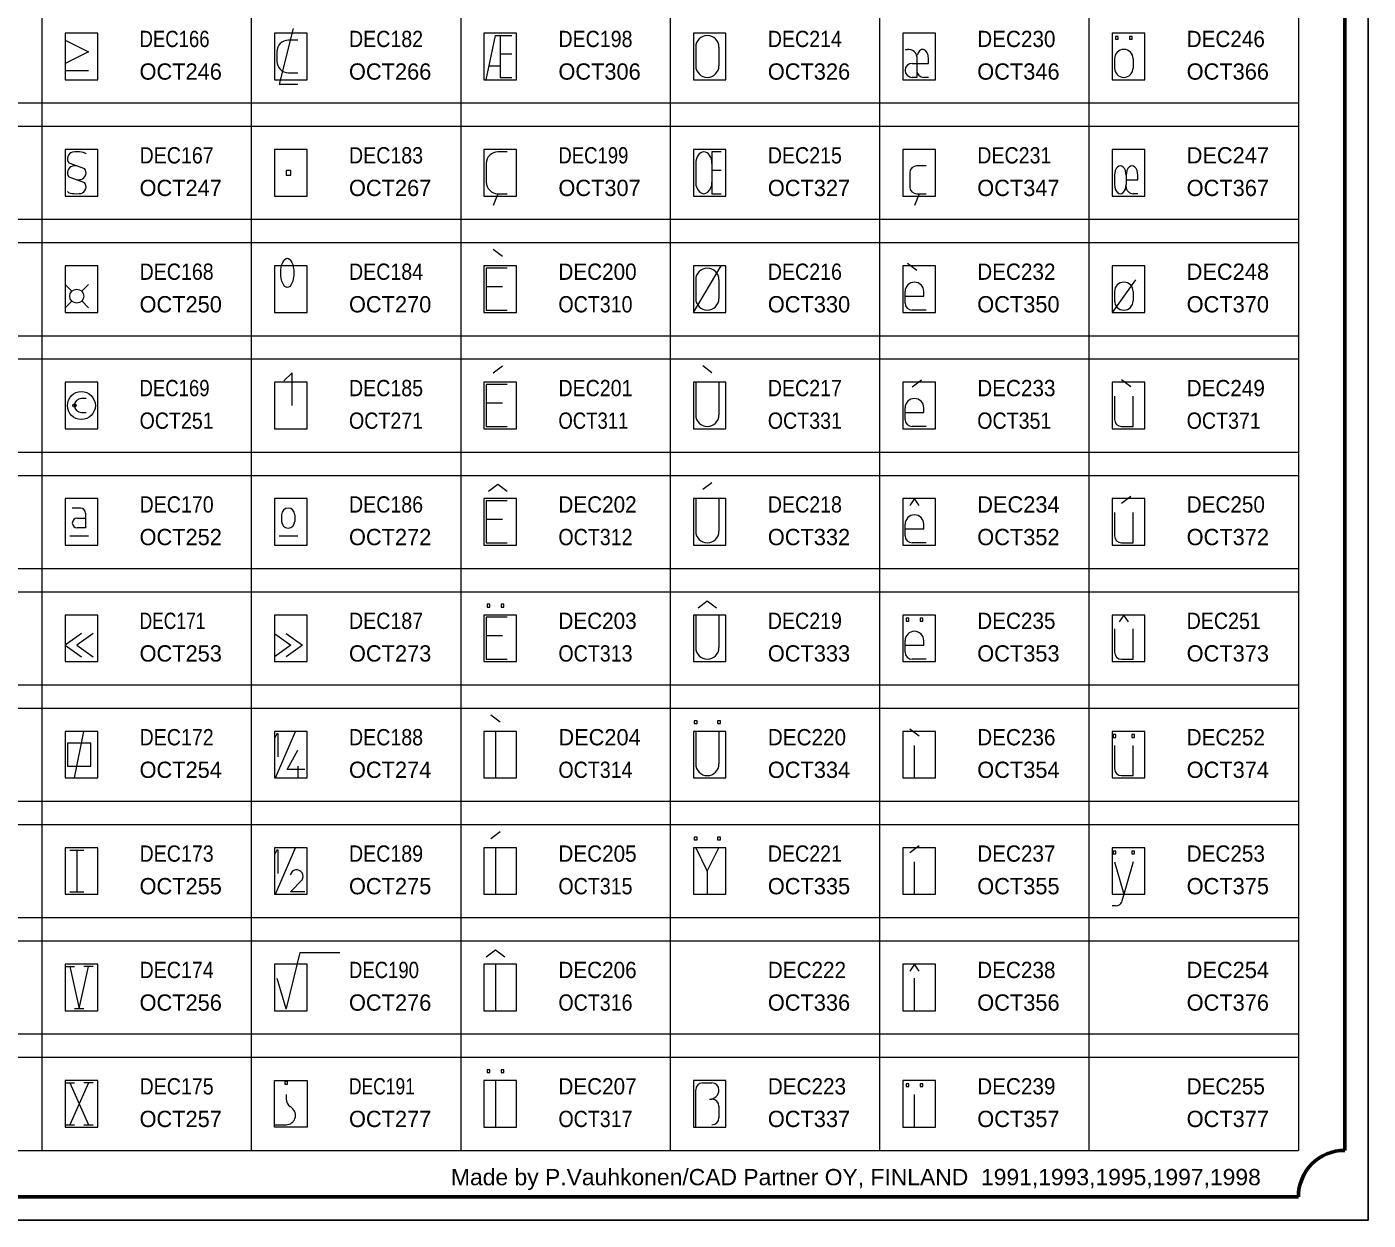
# Model space of a CAD drawing. Extents: x -200 to 7300, y -200 to 4800.
# Drawn here: x 4418 to 7300, y -200 to 2364 of the extents above; entities that cross this region are included whole.
import ezdxf
from ezdxf.enums import TextEntityAlignment as Align

# ---------------------------------------------------------------- set-up
doc = ezdxf.new("R2010")
doc.units = 0
doc.header["$LTSCALE"] = 14
doc.header["$PDMODE"] = 32
doc.header["$PDSIZE"] = 7
for name, color, linetype, lineweight in [('1', 7, 'Continuous', 13), ('5', 7, 'Continuous', 40), ('6', 7, 'Continuous', 13), ('63', 7, 'Continuous', 13)]:
    doc.layers.add(name, color=color, linetype=linetype, lineweight=lineweight)
doc.layers.add('10', color=7, linetype='Continuous')
doc.layers.add('11', color=7, linetype='Continuous')

msp = doc.modelspace()

# ---------------------------------------------------------------- linework, layer by layer
at = {"layer": '1'}
for p, q in [((5000, 2335), (4980, 2335)), ((4955, 2310), (4955, 2290)), ((5855, 2320), (5855, 2280)), ((5905, 2320), (5905, 2280)), ((6305, 2315), (6310, 2315)), ((5411, 2280), (5435, 2280)), ((5460, 2305), (5435, 2305)), ((6755, 2295), (6755, 2275)), ((6795, 2295), (6795, 2275)), ((4500, 2270), (4550, 2270)), ((4980, 2265), (5000, 2265)), ((6355, 2255), (6345, 2255)), ((5450, 2095), (5430, 2095)), ((4508, 2071), (4542, 2059)), ((5405, 2070), (5405, 2030)), ((5855, 2070), (5855, 2030)), ((5910, 2055), (5890, 2055)), ((6315, 2050), (6315, 2020)), ((6350, 2065), (6330, 2065)), ((4508, 2041), (4542, 2029)), ((6755, 2045), (6755, 2025)), ((6780, 2045), (6780, 2025)), ((5430, 2005), (5420, 1980)), ((5430, 2005), (5450, 2005)), ((6335, 2005), (6325, 1980)), ((6330, 2005), (6350, 2005)), ((6805, 2005), (6795, 2005)), ((5440, 1870), (5420, 1885)), ((5850, 1750), (5910, 1850)), ((6330, 1840), (6310, 1855)), ((5855, 1820), (5855, 1780)), ((5905, 1820), (5905, 1780)), ((6800, 1820), (6750, 1750)), ((4500, 1810), (4514.4, 1795.6)), ((4550, 1810), (4535.6, 1795.6)), ((5440, 1805), (5405, 1805)), ((6305, 1770), (6305, 1795)), ((6755, 1795), (6755, 1775)), ((6795, 1795), (6795, 1775)), ((4500, 1760), (4514.4, 1774.4)), ((4550, 1760), (4536, 1775)), ((6350, 1755), (6320, 1755)), ((5420, 1620), (5440, 1635)), ((5890, 1620), (5870, 1635)), ((5855, 1600), (5855, 1530)), ((5905, 1600), (5905, 1530)), ((6320, 1590), (6340, 1605)), ((6790, 1590), (6770, 1605)), ((4545, 1565), (4535, 1565)), ((6755, 1570), (6755, 1520)), ((4535, 1535), (4545, 1535)), ((5440, 1555), (5405, 1555)), ((6305, 1520), (6305, 1545)), ((6350, 1505), (6320, 1505)), ((5870, 1370), (5890, 1385)), ((6770, 1340), (6790, 1355)), ((4515, 1330), (4533, 1330)), ((5855, 1350), (5855, 1280)), ((5905, 1350), (5905, 1280)), ((4526, 1308), (4544, 1308)), ((4965, 1315.4), (4965, 1301.1)), ((4993.6, 1315.4), (4993.6, 1301.1)), ((5440, 1305), (5405, 1305)), ((6755, 1320), (6755, 1270)), ((4510, 1270), (4550, 1270)), ((4960, 1270), (5000, 1270)), ((6305, 1270), (6305, 1295)), ((6350, 1255), (6320, 1255)), ((5855, 1100), (5855, 1030)), ((5905, 1100), (5905, 1030)), ((6755, 1070), (6755, 1020)), ((5440, 1055), (5405, 1055)), ((6305, 1020), (6305, 1045)), ((6350, 1005), (6320, 1005)), ((5435, 870), (5415, 885)), ((4520, 750), (4540, 850)), ((4952, 750), (4995, 850)), ((5425, 850), (5425, 750)), ((5855, 850), (5855, 780)), ((5905, 850), (5905, 780)), ((6335, 840), (6315, 855)), ((6325, 750), (6325, 820)), ((6755, 820), (6755, 770)), ((5001, 750), (5001, 775)), ((5415, 620), (5435, 635)), ((4510, 595), (4540, 595)), ((4525, 595), (4525, 505)), ((4952, 500), (4995, 600)), ((5425, 600), (5425, 500)), ((6315, 590), (6335, 605)), ((5880, 550), (5880, 500)), ((6325, 500), (6325, 570)), ((6755, 570), (6775, 500)), ((6795, 570), (6771, 485)), ((4510, 505), (4540, 505)), ((6757, 475), (6750, 475)), ((5425, 350), (5425, 250)), ((4500, 345), (4520, 345)), ((4560, 345), (4540, 345)), ((6325, 250), (6325, 320)), ((4520, 255), (4540, 255)), ((4500, 95), (4520, 95)), ((4510, 95), (4550, 5)), ((4550, 95), (4510, 5)), ((4560, 95), (4540, 95)), ((5425, 100), (5425, 0)), ((5870, 95), (5890, 95)), ((4975, 70), (4975, 61)), ((5855, 0), (5855, 80)), ((5885, 60), (5890, 60)), ((6325, 0), (6325, 70)), ((4984, 44), (4987, 41)), ((5905, 45), (5905, 20)), ((4500, 5), (4520, 5)), ((4540, 5), (4560, 5)), ((4950, 5), (4975, 5))]:
    msp.add_line(p, q, dxfattribs=at)
for points in [[(4500, 2335), (4550, 2310), (4500, 2285)], [(4990, 2360), (4960, 2240), (5000, 2240)], [(5405, 2250), (5425, 2345), (5460, 2345)], [(5435, 2345), (5435, 2255), (5460, 2255)], [(6330, 2300), (6330, 2255), (6320, 2255)], [(6320, 2285), (6355, 2285), (6355, 2295)], [(5910, 2095), (5890, 2095), (5890, 2005), (5910, 2005)], [(6780, 2035), (6805, 2035), (6805, 2045)], [(5450, 1845), (5405, 1845), (5405, 1755), (5450, 1755)], [(6305, 1785), (6345, 1785), (6345, 1795)], [(4988, 1550), (4988, 1620), (4970, 1603)], [(5450, 1595), (5405, 1595), (5405, 1505), (5450, 1505)], [(6770, 1505), (6795, 1505), (6795, 1570)], [(6305, 1535), (6345, 1535), (6345, 1545)], [(5450, 1365), (5430, 1380), (5410, 1365)], [(5450, 1345), (5405, 1345), (5405, 1255), (5450, 1255)], [(6335, 1335), (6325, 1350), (6315, 1335)], [(4544, 1319), (4544, 1287), (4526, 1287)], [(6770, 1255), (6795, 1255), (6795, 1320)], [(6305, 1285), (6345, 1285), (6345, 1295)], [(5900, 1115), (5880, 1130), (5860, 1115)], [(6785, 1085), (6775, 1100), (6765, 1085)], [(5450, 1095), (5405, 1095), (5405, 1005), (5450, 1005)], [(6770, 1005), (6795, 1005), (6795, 1070)], [(4535, 1060), (4500, 1035), (4535, 1010)], [(4560, 1060), (4525, 1035), (4560, 1010)], [(4950, 1060), (4985, 1035), (4950, 1010)], [(4975, 1060), (5010, 1035), (4975, 1010)], [(6305, 1035), (6345, 1035), (6345, 1045)], [(4958, 795), (4958, 845), (4955, 845), (4950, 835)], [(5015, 768), (4977, 768), (5000, 810)], [(6770, 755), (6795, 755), (6795, 820)], [(4958, 545), (4958, 595), (4955, 595), (4950, 585)], [(5855, 600), (5880, 550), (5905, 600)], [(5015, 505), (4984, 505), (5009.3, 530.9)], [(4955, 320), (4974, 255), (4976, 255), (5005, 375), (5090, 375)], [(5445, 365), (5425, 380), (5405, 365)], [(6335, 335), (6325, 350), (6315, 335)], [(4510, 345), (4530, 255), (4550, 345)]]:
    msp.add_lwpolyline(points, dxfattribs=at)
for points in [[(6757, 2337), (6763, 2337), (6763, 2343), (6757, 2343)], [(6787, 2337), (6793, 2337), (6793, 2343), (6787, 2343)], [(4975, 2045), (4985, 2045), (4985, 2055), (4975, 2055)], [(5407, 1117), (5413, 1117), (5413, 1123), (5407, 1123)], [(5437, 1117), (5443, 1117), (5443, 1123), (5437, 1123)], [(6307, 1087), (6313, 1087), (6313, 1093), (6307, 1093)], [(6337, 1087), (6343, 1087), (6343, 1093), (6337, 1093)], [(5852, 867), (5858, 867), (5858, 873), (5852, 873)], [(5902, 867), (5908, 867), (5908, 873), (5902, 873)], [(6752, 837), (6758, 837), (6758, 843), (6752, 843)], [(6792, 837), (6798, 837), (6798, 843), (6792, 843)], [(4505, 775), (4555, 775), (4555, 825), (4505, 825)], [(5852, 617), (5858, 617), (5858, 623), (5852, 623)], [(5902, 617), (5908, 617), (5908, 623), (5902, 623)], [(6752, 587), (6758, 587), (6758, 593), (6752, 593)], [(6792, 587), (6798, 587), (6798, 593), (6792, 593)], [(5407, 117), (5413, 117), (5413, 123), (5407, 123)], [(5437, 117), (5443, 117), (5443, 123), (5437, 123)], [(4972, 92), (4978, 92), (4978, 98), (4972, 98)], [(6307, 87), (6313, 87), (6313, 93), (6307, 93)], [(6337, 87), (6343, 87), (6343, 93), (6337, 93)]]:
    msp.add_lwpolyline(points, close=True, dxfattribs=at)
for centre, radius in [((4525, 1785), 15), ((4535, 1550), 30)]:
    msp.add_circle(centre, radius, dxfattribs=at)
for centre, radius, start, end in [((4980, 2310), 25, 90, 180), ((5880, 2320), 25, 0, 180), ((6775, 2295), 20, 0, 180), ((4980, 2290), 25, 180, 270), ((5880, 2280), 25, 180, 360), ((6320, 2270), 15, 90, 270), ((6345, 2270), 15, 180, 270), ((6775, 2275), 20, 180, 360), ((4520, 2080), 15, 105.9454, 216.8699), ((5430, 2070), 25, 90, 180), ((4520, 2050), 15, 105.9454, 216.8699), ((4530, 2050), 15, 285.9566, 36.8811), ((6330, 2050), 15, 90, 180), ((4530, 2020), 15, 285.9454, 36.8699), ((5430, 2030), 25, 180, 270), ((6330, 2020), 15, 180, 270), ((6795, 2020), 15, 178.7175, 270), ((5880, 1820), 25, 0, 180), ((6325, 1795), 20, 0, 180), ((6775, 1795), 20, 0, 180), ((5880, 1780), 25, 180, 360), ((6320, 1770), 15, 180, 270), ((6775, 1775), 20, 180, 360), ((4535, 1550), 15, 90, 180), ((6325, 1545), 20, 0, 180), ((4535, 1550), 15, 180, 270), ((5880, 1530), 25, 180, 360), ((6320, 1520), 15, 180, 270), ((6770, 1520), 15, 180, 270), ((4533, 1319), 10.7, 0, 90), ((4979.3, 1315.4), 14.3, 0, 180), ((4526, 1297.5), 10.5, 90, 270), ((4979.3, 1301.1), 14.3, 180, 360), ((6325, 1295), 20, 0, 180), ((5880, 1280), 25, 180, 360), ((6320, 1270), 15, 180, 270), ((6770, 1270), 15, 180, 270), ((6325, 1045), 20, 0, 180), ((5880, 1030), 25, 180, 360), ((6320, 1020), 15, 180, 270), ((6770, 1020), 15, 180, 270), ((5880, 780), 25, 180, 360), ((6770, 770), 15, 180, 270), ((4997.5, 538.5), 14, 327.0948, 165.9638), ((6757.1, 490), 15, 270, 338.5769), ((5870, 80), 15, 90, 180), ((5890, 80), 15, 0, 90), ((4995, 60.7), 20, 180, 236.3099), ((5885, 80), 20, 270, 360), ((5890, 45), 15, 0, 90), ((4975, 25), 20, 270, 53.1301), ((5890, 20), 15, 270, 0)]:
    msp.add_arc(centre, radius, start, end, dxfattribs=at)
for centre, major_axis, ratio, start_param, end_param in [((6310, 2300), (20, 0), 0.75, 6.265764, 7.853982), ((6342.5, 2295), (0, -20), 0.6245, 1.570796, 4.375964), ((4525, 2090), (-20, 0), 0.25, 3.141593, 5.175477), ((5872.5, 2070), (0, 25), 0.7, 4.712389, 7.853981), ((4525, 2060), (-20, 0), 0.25, 4.712389, 5.175477), ((6767.5, 2045), (0, 20), 0.625, 4.712389, 7.853982), ((6792.5, 2045), (0, 20), 0.625, 4.712389, 7.853982), ((4525, 2040), (-20, 0), 0.25, 1.570796, 2.042096), ((5872.5, 2030), (0, 25), 0.7, 1.570796, 4.712389), ((6767.5, 2025), (0, 20), 0.625, 1.570796, 4.712389), ((4525, 2010), (-20, 0), 0.25, 6.283185, 8.366371)]:
    msp.add_ellipse(centre, major_axis=major_axis, ratio=ratio, start_param=start_param, end_param=end_param, dxfattribs=at)
msp.add_ellipse((4977.5, 1835), major_axis=(0, -31.5), ratio=0.444444, dxfattribs=at)
msp.add_point((4520, 1550), dxfattribs=at)
at = {"layer": '5', "lineweight": 53}
for p, q in [((7250, 4650), (7250, -50)), ((7150, -150), (-50, -150))]:
    msp.add_line(p, q, dxfattribs=at)
at = {"layer": '5', "lineweight": 25}
msp.add_lwpolyline([(-200, -200), (-200, 4800), (7300, 4800), (7300, -200)], close=True, dxfattribs=at)
at = {"layer": '5', "lineweight": 53}
msp.add_arc((7250, -150), 100, 90, 180, dxfattribs=at)
at = {"layer": '6'}
for p, q in [((4450, 3950), (4450, -50)), ((4900, 3950), (4900, -50)), ((5350, 3950), (5350, -50)), ((5800, 3950), (5800, -50)), ((6250, 3950), (6250, -50)), ((6700, 3950), (6700, -50)), ((7150, 3950), (7150, -50)), ((-50, 2200), (7150, 2200)), ((-50, 2150), (7150, 2150)), ((-50, 1950), (7150, 1950)), ((-50, 1900), (7150, 1900)), ((-50, 1700), (7150, 1700)), ((-50, 1650), (7150, 1650)), ((-50, 1450), (7150, 1450)), ((-50, 1400), (7150, 1400)), ((-50, 1200), (7150, 1200)), ((-50, 1150), (7150, 1150)), ((-50, 950), (7150, 950)), ((-50, 900), (7150, 900)), ((-50, 700), (7150, 700)), ((-50, 650), (7150, 650)), ((-50, 450), (7150, 450)), ((-50, 400), (7150, 400)), ((-50, 200), (7150, 200)), ((-50, 150), (7150, 150)), ((-50, -50), (7150, -50))]:
    msp.add_line(p, q, dxfattribs=at)
at = {"layer": '63'}
for points in [[(4500, 2250), (4570, 2250), (4570, 2350), (4500, 2350)], [(4950, 2250), (5020, 2250), (5020, 2350), (4950, 2350)], [(5400, 2250), (5470, 2250), (5470, 2350), (5400, 2350)], [(5850, 2250), (5920, 2250), (5920, 2350), (5850, 2350)], [(6300, 2250), (6370, 2250), (6370, 2350), (6300, 2350)], [(6750, 2250), (6820, 2250), (6820, 2350), (6750, 2350)], [(4500, 2000), (4570, 2000), (4570, 2100), (4500, 2100)], [(4950, 2000), (5020, 2000), (5020, 2100), (4950, 2100)], [(5400, 2000), (5470, 2000), (5470, 2100), (5400, 2100)], [(5850, 2000), (5920, 2000), (5920, 2100), (5850, 2100)], [(6300, 2000), (6370, 2000), (6370, 2100), (6300, 2100)], [(6750, 2000), (6820, 2000), (6820, 2100), (6750, 2100)], [(4500, 1750), (4570, 1750), (4570, 1850), (4500, 1850)], [(4950, 1750), (5020, 1750), (5020, 1850), (4950, 1850)], [(5400, 1750), (5470, 1750), (5470, 1850), (5400, 1850)], [(5850, 1750), (5920, 1750), (5920, 1850), (5850, 1850)], [(6300, 1750), (6370, 1750), (6370, 1850), (6300, 1850)], [(6750, 1750), (6820, 1750), (6820, 1850), (6750, 1850)], [(4500, 1500), (4570, 1500), (4570, 1600), (4500, 1600)], [(4950, 1500), (5020, 1500), (5020, 1600), (4950, 1600)], [(5400, 1500), (5470, 1500), (5470, 1600), (5400, 1600)], [(5850, 1500), (5920, 1500), (5920, 1600), (5850, 1600)], [(6300, 1500), (6370, 1500), (6370, 1600), (6300, 1600)], [(6750, 1500), (6820, 1500), (6820, 1600), (6750, 1600)], [(4500, 1250), (4570, 1250), (4570, 1350), (4500, 1350)], [(4950, 1250), (5020, 1250), (5020, 1350), (4950, 1350)], [(5400, 1250), (5470, 1250), (5470, 1350), (5400, 1350)], [(5850, 1250), (5920, 1250), (5920, 1350), (5850, 1350)], [(6300, 1250), (6370, 1250), (6370, 1350), (6300, 1350)], [(6750, 1250), (6820, 1250), (6820, 1350), (6750, 1350)], [(4500, 1000), (4570, 1000), (4570, 1100), (4500, 1100)], [(4950, 1000), (5020, 1000), (5020, 1100), (4950, 1100)], [(5400, 1000), (5470, 1000), (5470, 1100), (5400, 1100)], [(5850, 1000), (5920, 1000), (5920, 1100), (5850, 1100)], [(6300, 1000), (6370, 1000), (6370, 1100), (6300, 1100)], [(6750, 1000), (6820, 1000), (6820, 1100), (6750, 1100)], [(4500, 750), (4570, 750), (4570, 850), (4500, 850)], [(4950, 750), (5020, 750), (5020, 850), (4950, 850)], [(5400, 750), (5470, 750), (5470, 850), (5400, 850)], [(5850, 750), (5920, 750), (5920, 850), (5850, 850)], [(6300, 750), (6370, 750), (6370, 850), (6300, 850)], [(6750, 750), (6820, 750), (6820, 850), (6750, 850)], [(4500, 500), (4570, 500), (4570, 600), (4500, 600)], [(4950, 500), (5020, 500), (5020, 600), (4950, 600)], [(5400, 500), (5470, 500), (5470, 600), (5400, 600)], [(5850, 500), (5920, 500), (5920, 600), (5850, 600)], [(6300, 500), (6370, 500), (6370, 600), (6300, 600)], [(6750, 500), (6820, 500), (6820, 600), (6750, 600)], [(4500, 250), (4570, 250), (4570, 350), (4500, 350)], [(4950, 250), (5020, 250), (5020, 350), (4950, 350)], [(5400, 250), (5470, 250), (5470, 350), (5400, 350)], [(6300, 250), (6370, 250), (6370, 350), (6300, 350)], [(4500, 0), (4570, 0), (4570, 100), (4500, 100)], [(4950, 100), (5020, 100), (5020, 0), (4950, 0)], [(5400, 0), (5470, 0), (5470, 100), (5400, 100)], [(5850, 0), (5920, 0), (5920, 100), (5850, 100)], [(6300, 0), (6370, 0), (6370, 100), (6300, 100)]]:
    msp.add_lwpolyline(points, close=True, dxfattribs=at)

# ---------------------------------------------------------------- texts
at = {"layer": '10'}
for s, width, p in [('DEC166', 0.85, (4660, 2320)), ('DEC182', 0.9, (5110, 2320)), ('DEC198', 0.9, (5560, 2320)), ('DEC214', 0.9, (6010, 2320)), ('DEC230', 0.95, (6460, 2320)), ('DEC246', 0.95, (6910, 2320)), ('DEC167', 0.9, (4660, 2070)), ('DEC183', 0.9, (5110, 2070)), ('DEC199', 0.85, (5560, 2070)), ('DEC215', 0.9, (6010, 2070)), ('DEC231', 0.9, (6460, 2070)), ('DEC168', 0.9, (4660, 1820)), ('DEC184', 0.9, (5110, 1820)), ('DEC200', 0.95, (5560, 1820)), ('DEC216', 0.9, (6010, 1820)), ('DEC232', 0.95, (6460, 1820)), ('DEC169', 0.85, (4660, 1570)), ('DEC185', 0.9, (5110, 1570)), ('DEC201', 0.9, (5560, 1570)), ('DEC217', 0.9, (6010, 1570)), ('DEC233', 0.95, (6460, 1570)), ('DEC249', 0.95, (6910, 1570)), ('DEC170', 0.9, (4660, 1320)), ('DEC186', 0.9, (5110, 1320)), ('DEC202', 0.95, (5560, 1320)), ('DEC218', 0.9, (6010, 1320)), ('DEC250', 0.95, (6910, 1320)), ('DEC171', 0.8, (4660, 1070)), ('DEC187', 0.9, (5110, 1070)), ('DEC203', 0.95, (5560, 1070)), ('DEC219', 0.9, (6010, 1070)), ('DEC235', 0.95, (6460, 1070)), ('DEC251', 0.9, (6910, 1070)), ('DEC172', 0.9, (4660, 820)), ('DEC188', 0.9, (5110, 820)), ('DEC220', 0.95, (6010, 820)), ('DEC236', 0.95, (6460, 820)), ('DEC252', 0.95, (6910, 820)), ('DEC173', 0.9, (4660, 570)), ('DEC189', 0.9, (5110, 570)), ('DEC205', 0.95, (5560, 570)), ('DEC221', 0.9, (6010, 570)), ('DEC237', 0.95, (6460, 570)), ('DEC253', 0.95, (6910, 570)), ('DEC174', 0.9, (4660, 320)), ('DEC190', 0.85, (5110, 320)), ('DEC206', 0.95, (5560, 320)), ('DEC222', 0.95, (6010, 320)), ('DEC238', 0.95, (6460, 320)), ('DEC175', 0.9, (4660, 70)), ('DEC191', 0.8, (5110, 70)), ('DEC207', 0.95, (5560, 70)), ('DEC223', 0.95, (6010, 70)), ('DEC239', 0.95, (6460, 70)), ('DEC255', 0.95, (6910, 70))]:
    msp.add_text(s, height=35, dxfattribs=dict(at, width=width)).set_placement(p)
for s, p in [('DEC247', (6910, 2070)), ('DEC248', (6910, 1820)), ('DEC234', (6460, 1320)), ('DEC204', (5560, 820)), ('DEC254', (6910, 320))]:
    msp.add_text(s, height=35, dxfattribs=at).set_placement(p)
at = {"layer": '11'}
for s, p in [('OCT246', (4660, 2250)), ('OCT266', (5110, 2250)), ('OCT306', (5560, 2250)), ('OCT326', (6010, 2250)), ('OCT346', (6460, 2250)), ('OCT366', (6910, 2250)), ('OCT247', (4660, 2000)), ('OCT267', (5110, 2000)), ('OCT307', (5560, 2000)), ('OCT327', (6010, 2000)), ('OCT347', (6460, 2000)), ('OCT367', (6910, 2000)), ('OCT250', (4660, 1750)), ('OCT270', (5110, 1750)), ('OCT330', (6010, 1750)), ('OCT350', (6460, 1750)), ('OCT370', (6910, 1750)), ('OCT252', (4660, 1250)), ('OCT272', (5110, 1250)), ('OCT332', (6010, 1250)), ('OCT352', (6460, 1250)), ('OCT372', (6910, 1250)), ('OCT253', (4660, 1000)), ('OCT273', (5110, 1000)), ('OCT333', (6010, 1000)), ('OCT353', (6460, 1000)), ('OCT373', (6910, 1000)), ('OCT254', (4660, 750)), ('OCT274', (5110, 750)), ('OCT334', (6010, 750)), ('OCT354', (6460, 750)), ('OCT374', (6910, 750)), ('OCT255', (4660, 500)), ('OCT275', (5110, 500)), ('OCT335', (6010, 500)), ('OCT355', (6460, 500)), ('OCT375', (6910, 500)), ('OCT256', (4660, 250)), ('OCT276', (5110, 250)), ('OCT336', (6010, 250)), ('OCT356', (6460, 250)), ('OCT376', (6910, 250)), ('OCT257', (4660, 0)), ('OCT277', (5110, 0)), ('OCT337', (6010, 0)), ('OCT357', (6460, 0)), ('OCT377', (6910, 0))]:
    msp.add_text(s, height=35, dxfattribs=at).set_placement(p)
for s, width, p in [('OCT310', 0.9, (5560, 1750)), ('OCT251', 0.9, (4660, 1500)), ('OCT271', 0.9, (5110, 1500)), ('OCT311', 0.85, (5560, 1500)), ('OCT331', 0.9, (6010, 1500)), ('OCT351', 0.9, (6460, 1500)), ('OCT371', 0.9, (6910, 1500)), ('OCT312', 0.9, (5560, 1250)), ('OCT313', 0.9, (5560, 1000)), ('OCT314', 0.9, (5560, 750)), ('OCT315', 0.9, (5560, 500)), ('OCT316', 0.9, (5560, 250)), ('OCT317', 0.9, (5560, 0))]:
    msp.add_text(s, height=35, dxfattribs=dict(at, width=width)).set_placement(p)
at = {"layer": '5', "width": 1.05}
msp.add_text('Made by P.Vauhkonen/CAD Partner OY, FINLAND  1991,1993,1995,1997,1998', height=35, dxfattribs=at).set_placement((7069.3, -125), align=Align.RIGHT)

doc.saveas('drawing.dxf')
